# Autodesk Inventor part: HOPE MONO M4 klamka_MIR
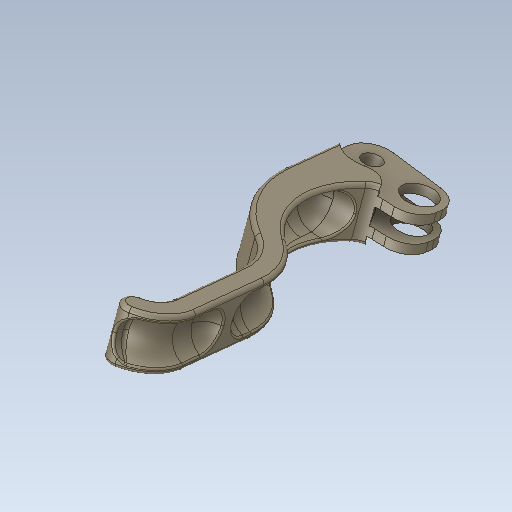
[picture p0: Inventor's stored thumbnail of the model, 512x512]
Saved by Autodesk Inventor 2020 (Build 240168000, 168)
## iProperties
Created: 2015-11
Part Number: HOPE MONO M4 klamka_MIR
Material: Ogólny
Document SubType Name: Modeling
Designer: Tomasz
Density: 1 g/cm^3
Appearance: Domyślna
Sending System: SolidWorks 2017
Last Author: Tomasz
Last Saved: 2017-10-01
Author: Tomasz
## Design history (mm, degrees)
feature "Imported1"
node "Bryła1"
